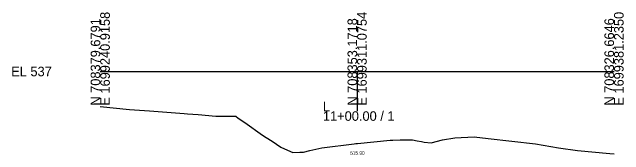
# Model space of a CAD drawing. Extents: x -63 to 1153, y -24 to 9522.
# Drawn here: x -25.7 to 152.8, y -24.4 to 17.4 of the extents above; entities that cross this region are included whole.
import ezdxf

# ---------------------------------------------------------------- set-up
doc = ezdxf.new("R2010")
doc.units = 0
for name, color, linetype in [('Default', 7, 'Continuous'), ('Exist Cross Section Cell', 7, 'Continuous'), ('Exist XS Center Line Elevation Label', 7, 'Continuous'), ('Exist XS Ground Line', 7, 'Continuous')]:
    doc.layers.add(name, color=color, linetype=linetype)

msp = doc.modelspace()

# ---------------------------------------------------------------- linework, layer by layer
at = {"layer": 'Exist Cross Section Cell'}
for p, q in [((0, 0), (75, 0)), ((75, 0), (150, 0)), ((75, 0), (75, -11.66))]:
    msp.add_line(p, q, dxfattribs=at)
at = {"layer": 'Exist XS Ground Line'}
msp.add_lwpolyline([(0, -10.22), (8.58, -11.11), (14.34, -11.55), (24.48, -12.32), (25.46, -12.4), (28.59, -12.65), (33.74, -13.13), (38.7, -13.1), (39.62, -13.14), (40.25, -13.67), (42.2, -14.94), (47.4, -18.7), (48.41, -19.3), (50.19, -20.46), (52.75, -22.14), (55.51, -23.4), (56.25, -23.78), (58.27, -23.65), (59.38, -23.6), (61.19, -23.17), (64.68, -22.39), (74.16, -21.2), (74.62, -21.14), (75, -21.1), (75.13, -21.09), (84.69, -20.14), (85.46, -20.13), (87.52, -20.02), (87.97, -20.03), (91.14, -20.06), (92.53, -20.34), (93.82, -20.54), (94.56, -20.68), (96.63, -20.86), (99.95, -20.01), (103.54, -19.42), (109.21, -19.19), (113.3, -19.63), (127.04, -21.16), (133.8, -22.42), (139.36, -23.17), (148.79, -24.03), (150, -24.1)], dxfattribs=at)

# ---------------------------------------------------------------- texts
at = {"layer": 'Default'}
msp.add_text('-', height=0.0001, dxfattribs=at).set_placement((0, 0))
at = {"layer": 'Exist Cross Section Cell'}
for s, p in [('E 1699240.9158', (2.8, -10)), ('E 1699311.0754', (77.8, -10)), ('E 1699381.2350', (152.8, -10)), ('N 708379.6791', (0, -10)), ('N 708353.1718', (75, -10)), ('N 708326.6646', (150, -10))]:
    msp.add_text(s, height=2.8, rotation=90, dxfattribs=at).set_placement(p)
for s, p in [('EL 537', (-26, -1.4)), ('L', (65, -11.66)), ('11+00.00 / 1', (65, -14.46))]:
    msp.add_text(s, height=2.8, dxfattribs=at).set_placement(p)
at = {"layer": 'Exist XS Center Line Elevation Label'}
msp.add_text('515.90', height=1, dxfattribs=at).set_placement((72.97, -24.4))

doc.saveas('drawing.dxf')
